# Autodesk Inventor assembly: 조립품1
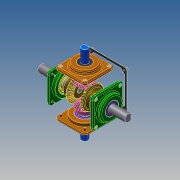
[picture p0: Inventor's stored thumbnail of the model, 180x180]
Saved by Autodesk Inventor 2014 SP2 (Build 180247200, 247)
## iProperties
Created: 2019-12
Part Number: 조립품1
Document SubType Name: Assembly
Designer: kb542-10
Author: kb542-10
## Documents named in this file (16)
- C:\Users\kb542-10\Desktop\391204V1038\조립품1.iam
- C:\Users\kb542-10\Desktop\391204V1038\본체.ipt
- C:\Users\kb542-10\Desktop\391204V1038\개스킷.ipt
- C:\Users\kb542-10\Desktop\391204V1038\메인베벨기어.ipt
- C:\Users\kb542-10\Desktop\391204V1038\메인축.ipt
- C:\Users\kb542-10\Desktop\391204V1038\메인커버.ipt
- C:\Users\kb542-10\Desktop\391204V1038\베어링 6203.ipt
- C:\Users\kb542-10\Desktop\391204V1038\베어링 6204.ipt
- C:\Users\kb542-10\Desktop\391204V1038\볼트 M4.ipt
- C:\Users\kb542-10\Desktop\391204V1038\상부커버.ipt
- C:\Users\kb542-10\Desktop\391204V1038\서브베벨기어.ipt
- C:\Users\kb542-10\Desktop\391204V1038\서브축.ipt
- C:\Users\kb542-10\Desktop\391204V1038\서브커버.ipt
- C:\Users\kb542-10\Desktop\391204V1038\오일 실 17 32 8.ipt
- C:\Users\kb542-10\Desktop\391204V1038\오일 실 20 35 8.ipt
- C:\Users\kb542-10\Desktop\391204V1038\키 4x4.ipt
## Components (1 placed, 1 different names)
1. 개스킷:1
